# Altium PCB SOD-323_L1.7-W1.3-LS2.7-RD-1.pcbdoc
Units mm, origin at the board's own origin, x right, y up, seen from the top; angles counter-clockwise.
Board outline 15.74 x 14.3 mm, 2 copper layers (Top Layer, Bottom Layer), stack 0 mm thick; 1 components, 0 nets, 2 pads, 0 vias.
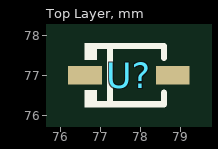
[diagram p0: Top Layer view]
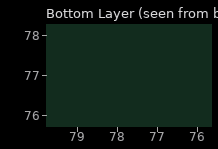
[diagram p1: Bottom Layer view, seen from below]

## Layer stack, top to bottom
Top Layer: signal copper (thickness not stored)
Bottom Layer: signal copper (thickness not stored)

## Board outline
85.59,69.85 69.85,69.85 69.85,84.155 85.59,84.155

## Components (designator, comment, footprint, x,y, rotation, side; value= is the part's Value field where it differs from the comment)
U? "" SOD-323_L1.7-W1.3-LS2.7-RD-1 77.72,77.002 r0 top

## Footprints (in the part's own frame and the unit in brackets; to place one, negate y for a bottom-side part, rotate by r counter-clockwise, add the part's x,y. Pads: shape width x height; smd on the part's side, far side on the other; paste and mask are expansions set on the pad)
SOD-323_L1.7-W1.3-LS2.7-RD-1 [mm]
  rect 0.845x0.455 smd: 1(-1.098,0) 2(1.097,0)
  silkscreen extent -1.1,-0.8 0.88,0.8

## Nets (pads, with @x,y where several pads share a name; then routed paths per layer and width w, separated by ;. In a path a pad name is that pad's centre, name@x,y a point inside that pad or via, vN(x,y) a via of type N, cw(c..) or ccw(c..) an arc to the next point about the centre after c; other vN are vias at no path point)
pads on no net: U?.1 U?.2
